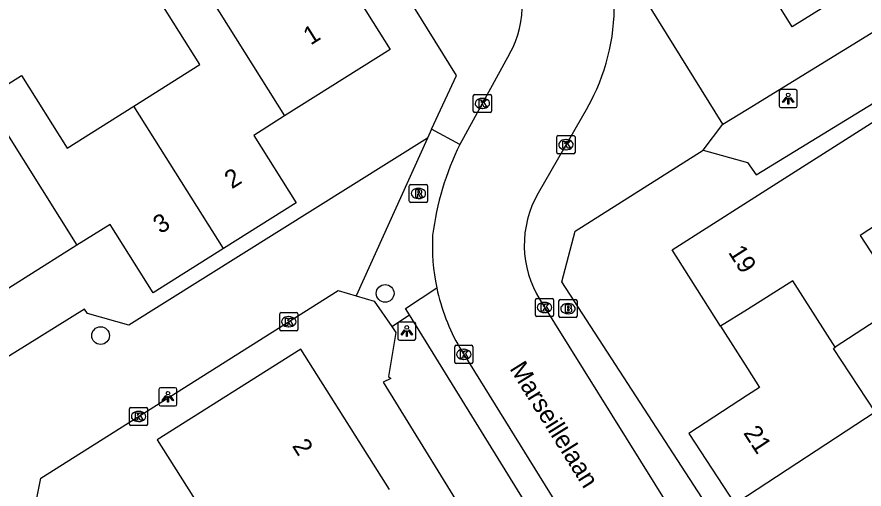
# Model space of a CAD drawing. Extents: x 158461 to 159795, y 387220 to 388672.
# Drawn here: x 158959.63 to 159006.44, y 387834.39 to 387860.45 of the extents above; entities that cross this region are included whole.
import ezdxf

# ---------------------------------------------------------------- set-up
doc = ezdxf.new("R2010")
doc.units = 0
for name, color, linetype in [('IMGEO_Boom', 7, 'Continuous'), ('IMGEO_Brandkraan', 7, 'Continuous'), ('IMGEO_Kolk', 7, 'Continuous'), ('IMGEO_Lichtpunt', 7, 'Continuous'), ('IMGEO_Openbare_ruimte_label', 7, 'Continuous'), ('IMGEO_Pand', 7, 'Continuous'), ('IMGEO_Pand_nummerreeks', 7, 'Continuous'), ('IMGEO_Rijbaan_lokaal_open', 7, 'Continuous'), ('IMGEO_Rioolput', 7, 'Continuous'), ('IMGEO_Voetpad_open', 7, 'Continuous')]:
    doc.layers.add(name, color=color, linetype=linetype)

msp = doc.modelspace()

# ---------------------------------------------------------------- linework, layer by layer
at = {"layer": 'IMGEO_Boom'}
for centre in [(158979.979, 387845.191), (158964.256, 387842.859)]:
    msp.add_circle(centre, 0.489, dxfattribs=at)
at = {"layer": 'IMGEO_Brandkraan'}
for p, q in [((158989.581, 387843.924), (158989.581, 387844.776)), ((158989.656, 387844.85), (158990.508, 387844.85)), ((158990.582, 387844.776), (158990.582, 387843.924)), ((158990.069, 387844.63), (158990.094, 387844.63)), ((158990.508, 387843.85), (158989.656, 387843.85)), ((158990.092, 387844.07), (158990.067, 387844.07))]:
    msp.add_line(p, q, dxfattribs=at)
for points in [[(158989.581, 387843.924), (158989.581, 387844.776)], [(158989.656, 387844.85), (158990.508, 387844.85)], [(158990.582, 387844.776), (158990.582, 387843.924)], [(158989.929, 387844.55), (158989.929, 387844.15), (158990.142, 387844.15)], [(158990.16, 387844.55), (158989.929, 387844.55)], [(158990.108, 387844.469), (158990.054, 387844.469), (158990.054, 387844.393)], [(158990.054, 387844.393), (158990.107, 387844.393)], [(158990.116, 387844.317), (158990.054, 387844.317), (158990.054, 387844.236)], [(158990.054, 387844.236), (158990.116, 387844.236)], [(158990.508, 387843.85), (158989.656, 387843.85)]]:
    msp.add_lwpolyline(points, dxfattribs=at)
for centre, radius, start, end in [((158989.658, 387844.774), 0.0765, 91.552, 178.448), ((158989.658, 387844.774), 0.0765, 91.552, 178.448), ((158990.506, 387844.774), 0.0765, 1.552, 88.448), ((158990.506, 387844.774), 0.0765, 1.552, 88.448), ((158990.109, 387844.431), 0.0379, 267.8285, 90.9355), ((158990.117, 387844.276), 0.0404, 269.8759, 90.5077), ((158990.164, 387844.405), 0.145, 59.4692, 91.5367), ((158990.189, 387844.452), 0.0922, 285.5137, 58.1501), ((158990.194, 387844.26), 0.105, 301.3115, 78.989), ((158989.658, 387843.926), 0.0765, 181.552, 268.448), ((158989.658, 387843.926), 0.0765, 181.552, 268.448), ((158990.148, 387844.401), 0.251, 268.6676, 293.5347), ((158990.506, 387843.926), 0.0765, 271.552, 358.448), ((158990.506, 387843.926), 0.0765, 271.552, 358.448)]:
    msp.add_arc(centre, radius, start, end, dxfattribs=at)
for centre, major_axis, ratio, start_param, end_param in [((158990.068, 387844.35), (-0.387, 0.002), 0.722429, 4.712389, 7.853982), ((158990.093, 387844.35), (-0.39, 0.002), 0.717154, 1.570796, 4.712389)]:
    msp.add_ellipse(centre, major_axis=major_axis, ratio=ratio, start_param=start_param, end_param=end_param, dxfattribs=at)
at = {"layer": 'IMGEO_Kolk'}
for p, q in [((158984.849, 387855.248), (158984.849, 387856.1)), ((158984.924, 387856.174), (158985.776, 387856.174)), ((158985.337, 387855.954), (158985.362, 387855.954)), ((158985.85, 387856.1), (158985.85, 387855.248)), ((158985.776, 387855.174), (158984.924, 387855.174)), ((158985.36, 387855.394), (158985.335, 387855.394)), ((158989.47, 387852.971), (158989.47, 387853.823)), ((158989.545, 387853.897), (158990.397, 387853.897)), ((158989.958, 387853.677), (158989.983, 387853.677)), ((158990.471, 387853.823), (158990.471, 387852.971)), ((158989.981, 387853.117), (158989.956, 387853.117)), ((158990.397, 387852.897), (158989.545, 387852.897)), ((158988.288, 387843.985), (158988.288, 387844.837)), ((158988.363, 387844.911), (158989.215, 387844.911)), ((158988.776, 387844.691), (158988.801, 387844.691)), ((158989.289, 387844.837), (158989.289, 387843.985)), ((158974.151, 387843.2), (158974.151, 387844.052)), ((158974.226, 387844.126), (158975.078, 387844.126)), ((158974.639, 387843.906), (158974.664, 387843.906)), ((158975.152, 387844.052), (158975.152, 387843.2)), ((158989.215, 387843.911), (158988.363, 387843.911)), ((158988.799, 387844.131), (158988.774, 387844.131)), ((158974.662, 387843.346), (158974.637, 387843.346)), ((158975.078, 387843.126), (158974.226, 387843.126)), ((158983.898, 387842.323), (158984.75, 387842.323)), ((158983.823, 387841.397), (158983.823, 387842.249)), ((158984.311, 387842.103), (158984.336, 387842.103)), ((158984.824, 387842.249), (158984.824, 387841.397)), ((158984.334, 387841.543), (158984.309, 387841.543)), ((158984.75, 387841.323), (158983.898, 387841.323)), ((158965.855, 387837.972), (158965.855, 387838.824)), ((158965.93, 387838.898), (158966.782, 387838.898)), ((158966.343, 387838.678), (158966.368, 387838.678)), ((158966.856, 387838.824), (158966.856, 387837.972)), ((158966.366, 387838.118), (158966.341, 387838.118)), ((158966.782, 387837.898), (158965.93, 387837.898))]:
    msp.add_line(p, q, dxfattribs=at)
for points in [[(158984.849, 387855.248), (158984.849, 387856.1)], [(158984.924, 387856.174), (158985.776, 387856.174)], [(158985.85, 387856.1), (158985.85, 387855.248)], [(158985.17, 387855.874), (158985.293, 387855.874), (158985.293, 387855.723), (158985.423, 387855.874), (158985.587, 387855.874), (158985.441, 387855.723), (158985.594, 387855.474), (158985.442, 387855.474), (158985.357, 387855.638), (158985.293, 387855.571), (158985.293, 387855.474), (158985.17, 387855.474), (158985.17, 387855.874)], [(158985.776, 387855.174), (158984.924, 387855.174)], [(158989.47, 387852.971), (158989.47, 387853.823)], [(158989.545, 387853.897), (158990.397, 387853.897)], [(158989.791, 387853.597), (158989.914, 387853.597), (158989.914, 387853.446), (158990.044, 387853.597), (158990.208, 387853.597), (158990.062, 387853.446), (158990.215, 387853.197), (158990.063, 387853.197), (158989.978, 387853.361), (158989.914, 387853.294), (158989.914, 387853.197), (158989.791, 387853.197), (158989.791, 387853.597)], [(158990.471, 387853.823), (158990.471, 387852.971)], [(158990.397, 387852.897), (158989.545, 387852.897)], [(158988.288, 387843.985), (158988.288, 387844.837)], [(158988.363, 387844.911), (158989.215, 387844.911)], [(158989.289, 387844.837), (158989.289, 387843.985)], [(158988.609, 387844.611), (158988.732, 387844.611), (158988.732, 387844.46), (158988.862, 387844.611), (158989.026, 387844.611), (158988.88, 387844.46), (158989.033, 387844.211), (158988.881, 387844.211), (158988.796, 387844.375), (158988.732, 387844.308), (158988.732, 387844.211), (158988.609, 387844.211), (158988.609, 387844.611)], [(158974.151, 387843.2), (158974.151, 387844.052)], [(158974.226, 387844.126), (158975.078, 387844.126)], [(158974.472, 387843.826), (158974.595, 387843.826), (158974.595, 387843.675), (158974.725, 387843.826), (158974.889, 387843.826), (158974.743, 387843.675), (158974.896, 387843.426), (158974.744, 387843.426), (158974.659, 387843.59), (158974.595, 387843.523), (158974.595, 387843.426), (158974.472, 387843.426), (158974.472, 387843.826)], [(158975.152, 387844.052), (158975.152, 387843.2)], [(158989.215, 387843.911), (158988.363, 387843.911)], [(158975.078, 387843.126), (158974.226, 387843.126)], [(158983.898, 387842.323), (158984.75, 387842.323)], [(158983.823, 387841.397), (158983.823, 387842.249)], [(158984.144, 387842.023), (158984.267, 387842.023), (158984.267, 387841.872), (158984.397, 387842.023), (158984.561, 387842.023), (158984.415, 387841.872), (158984.568, 387841.623), (158984.416, 387841.623), (158984.331, 387841.787), (158984.267, 387841.72), (158984.267, 387841.623), (158984.144, 387841.623), (158984.144, 387842.023)], [(158984.824, 387842.249), (158984.824, 387841.397)], [(158984.75, 387841.323), (158983.898, 387841.323)], [(158965.855, 387837.972), (158965.855, 387838.824)], [(158965.93, 387838.898), (158966.782, 387838.898)], [(158966.176, 387838.598), (158966.299, 387838.598), (158966.299, 387838.447), (158966.429, 387838.598), (158966.593, 387838.598), (158966.447, 387838.447), (158966.6, 387838.198), (158966.448, 387838.198), (158966.363, 387838.362), (158966.299, 387838.295), (158966.299, 387838.198), (158966.176, 387838.198), (158966.176, 387838.598)], [(158966.856, 387838.824), (158966.856, 387837.972)], [(158966.782, 387837.898), (158965.93, 387837.898)]]:
    msp.add_lwpolyline(points, dxfattribs=at)
for centre, start, end in [((158984.926, 387856.098), 91.552, 178.448), ((158984.926, 387856.098), 91.552, 178.448), ((158985.774, 387856.098), 1.552, 88.448), ((158985.774, 387856.098), 1.552, 88.448), ((158984.926, 387855.25), 181.552, 268.448), ((158984.926, 387855.25), 181.552, 268.448), ((158985.774, 387855.25), 271.552, 358.448), ((158985.774, 387855.25), 271.552, 358.448), ((158989.547, 387853.821), 91.552, 178.448), ((158989.547, 387853.821), 91.552, 178.448), ((158990.395, 387853.821), 1.552, 88.448), ((158990.395, 387853.821), 1.552, 88.448), ((158989.547, 387852.973), 181.552, 268.448), ((158989.547, 387852.973), 181.552, 268.448), ((158990.395, 387852.973), 271.552, 358.448), ((158990.395, 387852.973), 271.552, 358.448), ((158988.365, 387844.835), 91.552, 178.448), ((158988.365, 387844.835), 91.552, 178.448), ((158989.213, 387844.835), 1.552, 88.448), ((158989.213, 387844.835), 1.552, 88.448), ((158974.228, 387844.05), 91.552, 178.448), ((158974.228, 387844.05), 91.552, 178.448), ((158975.076, 387844.05), 1.552, 88.448), ((158975.076, 387844.05), 1.552, 88.448), ((158988.365, 387843.987), 181.552, 268.448), ((158988.365, 387843.987), 181.552, 268.448), ((158989.213, 387843.987), 271.552, 358.448), ((158989.213, 387843.987), 271.552, 358.448), ((158974.228, 387843.202), 181.552, 268.448), ((158974.228, 387843.202), 181.552, 268.448), ((158975.076, 387843.202), 271.552, 358.448), ((158975.076, 387843.202), 271.552, 358.448), ((158983.9, 387842.247), 91.552, 178.448), ((158983.9, 387842.247), 91.552, 178.448), ((158984.748, 387842.247), 1.552, 88.448), ((158984.748, 387842.247), 1.552, 88.448), ((158983.9, 387841.399), 181.552, 268.448), ((158983.9, 387841.399), 181.552, 268.448), ((158984.748, 387841.399), 271.552, 358.448), ((158984.748, 387841.399), 271.552, 358.448), ((158965.932, 387838.822), 91.552, 178.448), ((158965.932, 387838.822), 91.552, 178.448), ((158966.78, 387838.822), 1.552, 88.448), ((158966.78, 387838.822), 1.552, 88.448), ((158965.932, 387837.974), 181.552, 268.448), ((158965.932, 387837.974), 181.552, 268.448), ((158966.78, 387837.974), 271.552, 358.448), ((158966.78, 387837.974), 271.552, 358.448)]:
    msp.add_arc(centre, 0.0765, start, end, dxfattribs=at)
for centre, major_axis, ratio, start_param, end_param in [((158985.336, 387855.674), (-0.387, 0.002), 0.722429, 4.712389, 7.853982), ((158985.361, 387855.674), (-0.39, 0.002), 0.717154, 1.570796, 4.712389), ((158989.957, 387853.397), (-0.387, 0.002), 0.722429, 4.712389, 7.853982), ((158989.982, 387853.397), (-0.39, 0.002), 0.717154, 1.570796, 4.712389), ((158988.775, 387844.411), (-0.387, 0.002), 0.722429, 4.712389, 7.853982), ((158988.8, 387844.411), (-0.39, 0.002), 0.717154, 1.570796, 4.712389), ((158974.638, 387843.626), (-0.387, 0.002), 0.722429, 4.712389, 7.853982), ((158974.663, 387843.626), (-0.39, 0.002), 0.717154, 1.570796, 4.712389), ((158984.31, 387841.823), (-0.387, 0.002), 0.722429, 4.712389, 7.853982), ((158984.335, 387841.823), (-0.39, 0.002), 0.717154, 1.570796, 4.712389), ((158966.342, 387838.398), (-0.387, 0.002), 0.722429, 4.712389, 7.853982), ((158966.367, 387838.398), (-0.39, 0.002), 0.717154, 1.570796, 4.712389)]:
    msp.add_ellipse(centre, major_axis=major_axis, ratio=ratio, start_param=start_param, end_param=end_param, dxfattribs=at)
at = {"layer": 'IMGEO_Lichtpunt'}
for p, q in [((159002.657, 387856.442), (159001.849, 387856.442)), ((159002.657, 387856.442), (159001.849, 387856.442)), ((159001.755, 387856.347), (159001.755, 387855.54)), ((159001.755, 387856.347), (159001.755, 387855.54)), ((159002.751, 387855.54), (159002.751, 387856.347)), ((159002.751, 387855.54), (159002.751, 387856.347)), ((159001.849, 387855.446), (159002.657, 387855.446)), ((159001.849, 387855.446), (159002.657, 387855.446)), ((158980.674, 387843.511), (158980.674, 387842.704)), ((158980.674, 387843.511), (158980.674, 387842.704)), ((158981.576, 387843.606), (158980.768, 387843.606)), ((158981.576, 387843.606), (158980.768, 387843.606)), ((158981.67, 387842.704), (158981.67, 387843.511)), ((158981.67, 387842.704), (158981.67, 387843.511)), ((158980.768, 387842.61), (158981.576, 387842.61)), ((158980.768, 387842.61), (158981.576, 387842.61)), ((158968.38, 387839.978), (158967.572, 387839.978)), ((158968.38, 387839.978), (158967.572, 387839.978)), ((158967.478, 387839.883), (158967.478, 387839.076)), ((158967.478, 387839.883), (158967.478, 387839.076)), ((158968.474, 387839.076), (158968.474, 387839.883)), ((158968.474, 387839.076), (158968.474, 387839.883)), ((158967.572, 387838.982), (158968.38, 387838.982)), ((158967.572, 387838.982), (158968.38, 387838.982))]:
    msp.add_line(p, q, dxfattribs=at)
for points in [[(159002.129, 387856.011), (159002.168, 387855.983), (159001.98, 387855.721), (159001.942, 387855.748), (159002.129, 387856.011)], [(159002.231, 387855.963), (159002.278, 387855.963), (159002.278, 387855.641), (159002.231, 387855.641), (159002.231, 387855.963)], [(159002.341, 387855.983), (159002.379, 387856.01), (159002.566, 387855.748), (159002.527, 387855.72), (159002.341, 387855.983)], [(158981.048, 387843.175), (158981.087, 387843.147), (158980.899, 387842.885), (158980.861, 387842.912), (158981.048, 387843.175)], [(158981.15, 387843.127), (158981.197, 387843.127), (158981.197, 387842.805), (158981.15, 387842.805), (158981.15, 387843.127)], [(158981.26, 387843.147), (158981.298, 387843.174), (158981.485, 387842.912), (158981.446, 387842.884), (158981.26, 387843.147)], [(158967.852, 387839.547), (158967.891, 387839.519), (158967.703, 387839.257), (158967.665, 387839.284), (158967.852, 387839.547)], [(158967.954, 387839.499), (158968.001, 387839.499), (158968.001, 387839.177), (158967.954, 387839.177), (158967.954, 387839.499)], [(158968.064, 387839.519), (158968.102, 387839.546), (158968.289, 387839.284), (158968.25, 387839.256), (158968.064, 387839.519)]]:
    msp.add_lwpolyline(points, dxfattribs=at)
for centre in [(159002.254, 387856.145), (158981.173, 387843.309), (158967.977, 387839.681)]:
    msp.add_circle(centre, 0.0994, dxfattribs=at)
for centre, start, end in [((159001.849, 387856.347), 90, 180), ((159001.849, 387856.347), 90, 180), ((159002.657, 387856.347), 0, 90), ((159002.657, 387856.347), 0, 90), ((159001.849, 387855.54), 180, 270), ((159001.849, 387855.54), 180, 270), ((159002.657, 387855.54), 270, 0), ((159002.657, 387855.54), 270, 360), ((158980.768, 387843.511), 90, 180), ((158980.768, 387843.511), 90, 180), ((158981.576, 387843.511), 0, 90), ((158981.576, 387843.511), 0, 90), ((158980.768, 387842.704), 180, 270), ((158980.768, 387842.704), 180, 270), ((158981.576, 387842.704), 270, 0), ((158981.576, 387842.704), 270, 360), ((158967.572, 387839.883), 90, 180), ((158967.572, 387839.883), 90, 180), ((158968.38, 387839.883), 0, 90), ((158968.38, 387839.883), 0, 90), ((158967.572, 387839.076), 180, 270), ((158967.572, 387839.076), 180, 270), ((158968.38, 387839.076), 270, 0), ((158968.38, 387839.076), 270, 360)]:
    msp.add_arc(centre, 0.0946, start, end, dxfattribs=at)
at = {"layer": 'IMGEO_Pand'}
for points in [[(159005.945, 387870.107), (159006.908, 387868.56), (159009.552, 387864.315), (159002.473, 387859.906), (159000, 387863.877), (158999.485, 387864.704), (158995.146, 387862.001)], [(158978.036, 387866.701), (158975.994, 387865.418), (158980.251, 387858.644), (158974.425, 387854.983)], [(158966.098, 387855.528), (158969.742, 387857.818), (158967.422, 387861.511), (158969.501, 387862.817)], [(158969.501, 387862.817), (158974.425, 387854.983)], [(158957.856, 387855.939), (158959.891, 387857.218), (158962.409, 387853.21), (158966.098, 387855.528)], [(158957.856, 387855.939), (158958.051, 387855.629), (158962.943, 387847.846)], [(158971.044, 387847.66), (158966.098, 387855.528)], [(158974.425, 387854.983), (158972.717, 387853.91), (158975.058, 387850.183), (158971.044, 387847.66)], [(158998.517, 387843.379), (158995.837, 387847.595), (159000, 387850.241), (159007.437, 387854.968), (159010.066, 387850.893), (159006.227, 387848.382), (159008.64, 387844.694), (159004.853, 387842.217)], [(158971.044, 387847.66), (158967.155, 387845.216), (158964.777, 387848.999), (158962.943, 387847.846)], [(158962.943, 387847.846), (158957.219, 387844.249)], [(159004.853, 387842.217), (159002.515, 387845.88), (159000, 387844.306), (158998.517, 387843.379)], [(158998.517, 387843.379), (159000, 387841.046), (159000.662, 387840.004), (159000, 387839.571), (158996.758, 387837.45), (158999.294, 387833.574)], [(158980.214, 387834.357), (158975.317, 387842.12), (158967.383, 387837.115), (158970.05, 387832.887), (158972.277, 387829.357)], [(159007.056, 387838.649), (159004.761, 387842.157), (159004.853, 387842.217)], [(158999.294, 387833.574), (159000, 387834.036), (159007.056, 387838.649)]]:
    msp.add_lwpolyline(points, dxfattribs=at)
at = {"layer": 'IMGEO_Rijbaan_lokaal_open'}
for points in [[(158986.858, 387858.411), (158984.103, 387853.413)], [(158991.152, 387855.446), (158988.435, 387850.729)], [(158982.548, 387854.251), (158982.324, 387853.764)], [(158984.103, 387853.413), (158982.548, 387854.251)], [(158982.324, 387853.764), (158965.813, 387843.44), (158963.534, 387844.082), (158963.364, 387844.322), (158954.674, 387838.921), (158954.804, 387838.611), (158953.773, 387835.863), (158942.863, 387829.034), (158940.204, 387829.546), (158940.104, 387829.896), (158931.823, 387824.723), (158932.103, 387824.393), (158931.212, 387821.716), (158925.021, 387817.862), (158924.603, 387818.533)], [(158982.324, 387853.764), (158978.385, 387845.055)], [(158960.771, 387825.263), (158959.448, 387827.391), (158960.945, 387834.987), (158977.391, 387845.351), (158978.385, 387845.055)], [(158981.32, 387843.998), (158981.1, 387844.353), (158982.833, 387845.501)], [(158978.385, 387845.055), (158979.38, 387844.759), (158980.343, 387843.358)], [(158988.539, 387844.814), (158997.248, 387830.851), (159000, 387826.408), (159004.448, 387819.226)], [(158980.343, 387843.358), (158981.32, 387843.998)], [(158984.098, 387842.186), (158990.441, 387831.966), (158996.175, 387822.765), (159000, 387816.635)]]:
    msp.add_lwpolyline(points, dxfattribs=at)
for centre, radius, start, end in [((158981.936, 387861.124), 5.62, 331.1354, 32.0815), ((158981.43, 387861.021), 11.207, 330.17, 1.2859), ((158998.552, 387846.35), 16.083, 153.9504, 172.6595), ((158993.417, 387847.858), 5.75, 150.05, 211.9646), ((158993.762, 387847.835), 11.176, 177.0784, 192.0569), ((158993.934, 387847.838), 11.345, 191.8901, 209.8835)]:
    msp.add_arc(centre, radius, start, end, dxfattribs=at)
at = {"layer": 'IMGEO_Rioolput'}
for p, q in [((158981.39, 387851.206), (158982.242, 387851.206)), ((158981.315, 387850.28), (158981.315, 387851.132)), ((158981.803, 387850.986), (158981.828, 387850.986)), ((158982.316, 387851.132), (158982.316, 387850.28)), ((158981.826, 387850.426), (158981.801, 387850.426)), ((158982.242, 387850.206), (158981.39, 387850.206))]:
    msp.add_line(p, q, dxfattribs=at)
for points in [[(158981.39, 387851.206), (158982.242, 387851.206)], [(158981.315, 387850.28), (158981.315, 387851.132)], [(158981.904, 387850.904), (158981.652, 387850.906), (158981.652, 387850.506)], [(158981.83, 387850.825), (158981.776, 387850.825), (158981.776, 387850.744)], [(158981.776, 387850.744), (158981.828, 387850.744)], [(158982.316, 387851.132), (158982.316, 387850.28)], [(158981.652, 387850.506), (158981.776, 387850.506), (158981.776, 387850.668), (158981.787, 387850.668)], [(158981.834, 387850.639), (158981.905, 387850.506), (158982.045, 387850.506), (158981.98, 387850.632)], [(158982.242, 387850.206), (158981.39, 387850.206)]]:
    msp.add_lwpolyline(points, dxfattribs=at)
for centre, radius, start, end in [((158981.392, 387851.13), 0.0765, 91.552, 178.448), ((158981.392, 387851.13), 0.0765, 91.552, 178.448), ((158982.24, 387851.13), 0.0765, 1.552, 88.448), ((158982.24, 387851.13), 0.0765, 1.552, 88.448), ((158981.812, 387850.933), 0.19, 274.7715, 282.9687), ((158981.836, 387850.729), 0.0964, 77.0061, 93.1865), ((158981.85, 387850.786), 0.0378, 276.6634, 79.6772), ((158981.903, 387850.794), 0.109, 350.3612, 89.416), ((158981.901, 387850.794), 0.112, 277.5842, 350.9817), ((158981.392, 387850.282), 0.0765, 181.552, 268.448), ((158981.392, 387850.282), 0.0765, 181.552, 268.448), ((158981.786, 387850.615), 0.0533, 26.0293, 88.6989), ((158981.885, 387850.579), 0.108, 29.5134, 73.7905), ((158982.24, 387850.282), 0.0765, 271.552, 358.448), ((158982.24, 387850.282), 0.0765, 271.552, 358.448)]:
    msp.add_arc(centre, radius, start, end, dxfattribs=at)
for centre, major_axis, ratio, start_param, end_param in [((158981.802, 387850.706), (-0.387, 0.002), 0.722429, 4.712389, 7.853982), ((158981.827, 387850.706), (-0.39, 0.002), 0.717154, 1.570796, 4.712389)]:
    msp.add_ellipse(centre, major_axis=major_axis, ratio=ratio, start_param=start_param, end_param=end_param, dxfattribs=at)
at = {"layer": 'IMGEO_Voetpad_open'}
for points in [[(158998.64, 387854.52), (159000, 387855.355), (159015.923, 387865.135), (159017.64, 387866.189), (159023.474, 387869.772), (159018.445, 387877.845), (159016.613, 387876.704), (159015.724, 387878.132)], [(158982.548, 387854.251), (158983.915, 387857.22), (158978.036, 387866.701)], [(158998.64, 387854.52), (158994.344, 387861.45), (158995.146, 387862.001)], [(158997.549, 387853.092), (159000, 387852.422), (159000.488, 387851.729), (159017.667, 387862.251)], [(158997.549, 387853.092), (158998.64, 387854.52)], [(159007.183, 387818.548), (159005.394, 387821.005), (159000, 387830.047), (158989.749, 387845.829), (158990.479, 387848.629), (158997.549, 387853.092)], [(159003.654, 387812.403), (159001.639, 387811.148), (159000, 387813.774), (158981.32, 387843.998)], [(158980.343, 387843.358), (158980.569, 387843.029), (158980.168, 387840.601), (158980.288, 387840.501), (158979.878, 387840.291), (158985.222, 387831.6), (158985.682, 387831.81), (158988.261, 387831.208), (159000, 387812.491), (159002.375, 387808.704)]]:
    msp.add_lwpolyline(points, dxfattribs=at)

# ---------------------------------------------------------------- texts
at = {"layer": 'IMGEO_Openbare_ruimte_label'}
msp.add_text('Marseillelaan', height=1, rotation=301.8778, dxfattribs=at).set_placement((158986.826, 387841.043))
at = {"layer": 'IMGEO_Pand_nummerreeks'}
for s, rotation, p in [('1', 32.1378, (158975.86, 387858.862)), ('2', 32.1492, (158971.506, 387850.928)), ('3', 32.1492, (158967.557, 387848.445)), ('19', 302.443, (158998.91, 387847.461)), ('21', 303.196, (158999.744, 387837.489)), ('2', 302.2465, (158974.811, 387836.775))]:
    msp.add_text(s, height=1, rotation=rotation, dxfattribs=at).set_placement(p)

doc.saveas('drawing.dxf')
